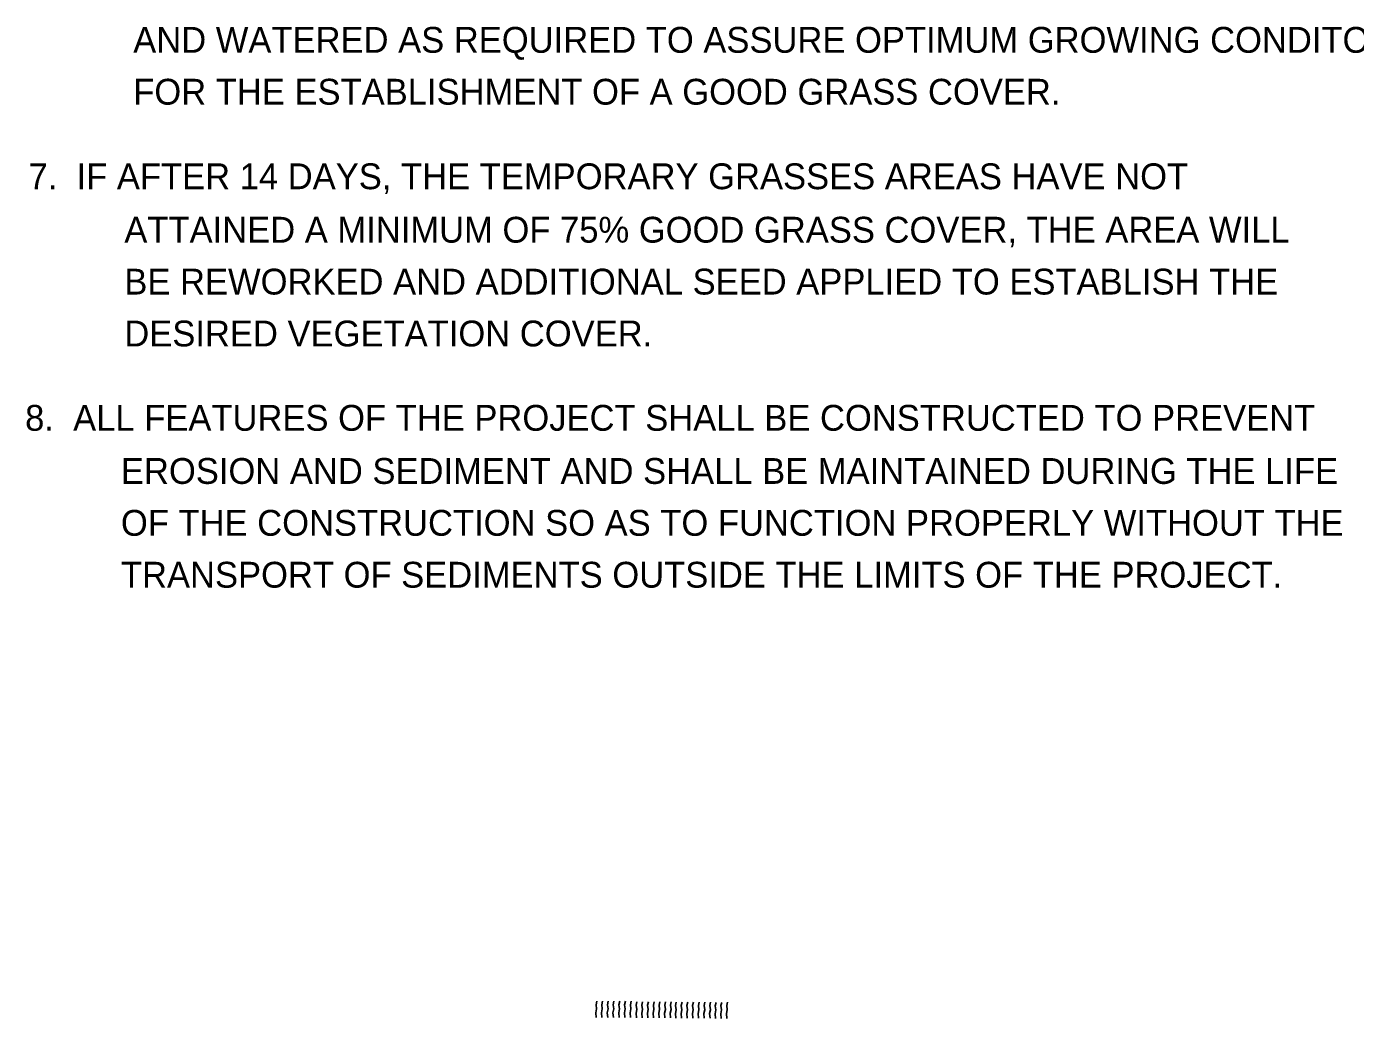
# Model space of a CAD drawing. Extents: x 539344 to 540004, y 1574686 to 1575110.
# Drawn here: x 539660.7 to 539789.3, y 1574801.9 to 1574897.8 of the extents above; entities that cross this region are included whole.
import ezdxf

# ---------------------------------------------------------------- set-up
doc = ezdxf.new("R2010")
doc.units = 0
doc.layers.add('Default', color=7, linetype='Continuous')

msp = doc.modelspace()

# ---------------------------------------------------------------- linework, layer by layer
at = {"layer": 'Default'}
for points in [[(539715.82, 1574801.97), (539715.78, 1574802.43), (539715.86, 1574802.79), (539715.8, 1574803.2), (539715.87, 1574803.53)], [(539716.37, 1574801.97), (539716.34, 1574802.43), (539716.41, 1574802.79), (539716.36, 1574803.2), (539716.43, 1574803.53)], [(539716.93, 1574801.97), (539716.89, 1574802.43), (539716.96, 1574802.79), (539716.91, 1574803.2), (539716.98, 1574803.53)], [(539717.48, 1574801.97), (539717.44, 1574802.43), (539717.52, 1574802.79), (539717.46, 1574803.2), (539717.53, 1574803.53)], [(539718.03, 1574801.97), (539718, 1574802.43), (539718.07, 1574802.79), (539718.02, 1574803.2), (539718.09, 1574803.53)], [(539718.59, 1574801.97), (539718.55, 1574802.43), (539718.62, 1574802.8), (539718.57, 1574803.2), (539718.64, 1574803.53)], [(539719.14, 1574801.97), (539719.1, 1574802.43), (539719.17, 1574802.79), (539719.12, 1574803.2), (539719.19, 1574803.53)], [(539719.71, 1574801.92), (539719.67, 1574802.38), (539719.75, 1574802.75), (539719.69, 1574803.15), (539719.76, 1574803.48)], [(539720.26, 1574801.92), (539720.22, 1574802.38), (539720.29, 1574802.75), (539720.24, 1574803.15), (539720.31, 1574803.48)], [(539720.81, 1574801.92), (539720.78, 1574802.38), (539720.85, 1574802.75), (539720.79, 1574803.15), (539720.87, 1574803.48)], [(539721.37, 1574801.92), (539721.33, 1574802.38), (539721.4, 1574802.75), (539721.35, 1574803.15), (539721.42, 1574803.48)], [(539721.92, 1574801.92), (539721.88, 1574802.38), (539721.95, 1574802.75), (539721.9, 1574803.15), (539721.97, 1574803.48)], [(539722.47, 1574801.92), (539722.43, 1574802.38), (539722.51, 1574802.74), (539722.45, 1574803.15), (539722.53, 1574803.48)], [(539723.02, 1574801.92), (539722.99, 1574802.38), (539723.06, 1574802.75), (539723, 1574803.15), (539723.08, 1574803.48)], [(539723.51, 1574801.89), (539723.48, 1574802.35), (539723.55, 1574802.72), (539723.49, 1574803.12), (539723.57, 1574803.45)], [(539724.06, 1574801.89), (539724.03, 1574802.35), (539724.1, 1574802.72), (539724.05, 1574803.12), (539724.12, 1574803.45)], [(539724.62, 1574801.89), (539724.58, 1574802.35), (539724.66, 1574802.72), (539724.6, 1574803.12), (539724.67, 1574803.45)], [(539725.17, 1574801.89), (539725.14, 1574802.35), (539725.21, 1574802.72), (539725.15, 1574803.12), (539725.23, 1574803.45)], [(539725.72, 1574801.89), (539725.69, 1574802.35), (539725.76, 1574802.72), (539725.7, 1574803.12), (539725.78, 1574803.45)], [(539726.28, 1574801.89), (539726.24, 1574802.35), (539726.32, 1574802.72), (539726.26, 1574803.12), (539726.33, 1574803.45)], [(539726.83, 1574801.89), (539726.79, 1574802.35), (539726.87, 1574802.72), (539726.81, 1574803.12), (539726.89, 1574803.45)], [(539727.36, 1574801.87), (539727.32, 1574802.33), (539727.4, 1574802.7), (539727.34, 1574803.1), (539727.41, 1574803.43)], [(539727.91, 1574801.87), (539727.88, 1574802.33), (539727.95, 1574802.7), (539727.89, 1574803.11), (539727.97, 1574803.43)], [(539728.47, 1574801.88), (539728.43, 1574802.34), (539728.5, 1574802.7), (539728.45, 1574803.11), (539728.52, 1574803.44)]]:
    msp.add_lwpolyline(points, dxfattribs=at)

# ---------------------------------------------------------------- texts
for s, p in [('AND WATERED AS REQUIRED TO ASSURE OPTIMUM GROWING CONDITONS', (539671.02, 1574895.3)), ('FOR THE ESTABLISHMENT OF A GOOD GRASS COVER.', (539671.02, 1574890.28)), ('7.  IF AFTER 14 DAYS, THE TEMPORARY GRASSES AREAS HAVE NOT', (539660.89, 1574882.1)), ('ATTAINED A MINIMUM OF 75% GOOD GRASS COVER, THE AREA WILL', (539670.16, 1574876.93)), ('BE REWORKED AND ADDITIONAL SEED APPLIED TO ESTABLISH THE', (539670.16, 1574871.91)), ('DESIRED VEGETATION COVER.', (539670.16, 1574866.89)), ('8.  ALL FEATURES OF THE PROJECT SHALL BE CONSTRUCTED TO PREVENT', (539660.56, 1574858.73)), ('EROSION AND SEDIMENT AND SHALL BE MAINTAINED DURING THE LIFE', (539669.83, 1574853.59)), ('OF THE CONSTRUCTION SO AS TO FUNCTION PROPERLY WITHOUT THE', (539669.83, 1574848.57)), ('TRANSPORT OF SEDIMENTS OUTSIDE THE LIMITS OF THE PROJECT.', (539669.83, 1574843.55))]:
    msp.add_text(s, height=2.5, dxfattribs=at).set_placement(p)

doc.saveas('drawing.dxf')
